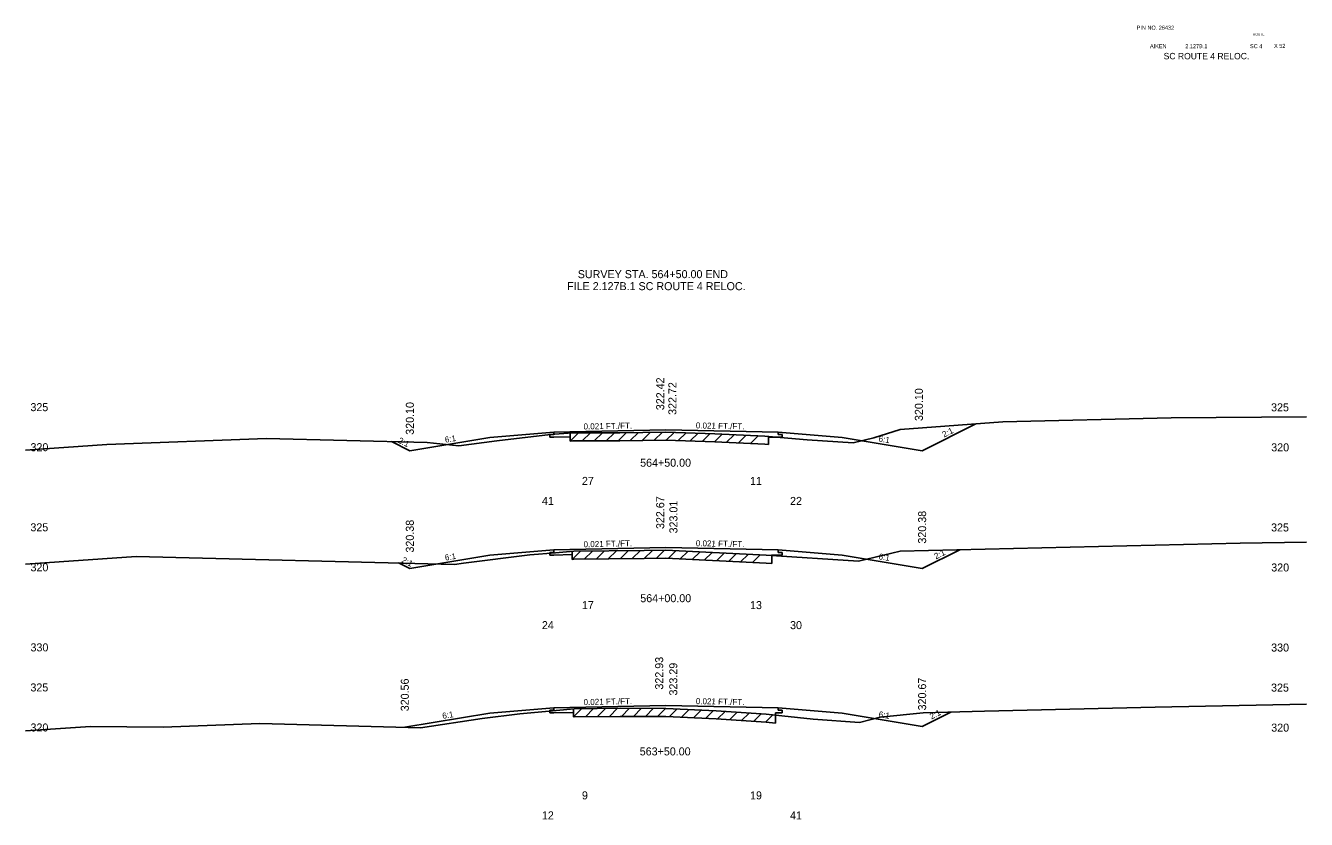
# Model space of a CAD drawing. Extents: x 2967 to 4323, y -3677 to -817.
# Drawn here: x 4005.3 to 4165.3, y -3560.8 to -3461.7 of the extents above; entities that cross this region are included whole.
import ezdxf

# ---------------------------------------------------------------- set-up
doc = ezdxf.new("R2010")
doc.units = 0
for name, color, linetype in [('Level 1', 7, 'Continuous'), ('Level 10', 7, 'Continuous'), ('Level 11', 7, 'Continuous'), ('Level 12', 7, 'Continuous'), ('Level 20', 7, 'Continuous'), ('Level 3', 7, 'Continuous'), ('Level 32', 7, 'Continuous'), ('Level 33', 7, 'Continuous'), ('Level 59', 7, 'Continuous'), ('Level 6', 7, 'Continuous'), ('Level 60', 7, 'Continuous'), ('Level 61', 7, 'Continuous'), ('Level 7', 7, 'Continuous')]:
    doc.layers.add(name, color=color, linetype=linetype)

msp = doc.modelspace()

# ---------------------------------------------------------------- linework, layer by layer
at = {"layer": 'Level 11'}
for p, q in [((4071.26, -3512.71), (4070.76, -3512.72)), ((4070.76, -3512.72), (4070.76, -3513.06)), ((4070.76, -3513.06), (4071.26, -3513.05)), ((4071.26, -3512.41), (4071.26, -3512.71)), ((4099.26, -3512.71), (4099.26, -3512.41)), ((4099.76, -3512.72), (4099.26, -3512.71)), ((4099.26, -3513.05), (4099.76, -3513.06)), ((4099.76, -3513.06), (4099.76, -3512.72)), ((4071.26, -3527.43), (4070.76, -3527.44)), ((4070.76, -3527.44), (4070.76, -3527.78)), ((4070.76, -3527.78), (4071.26, -3527.77)), ((4071.26, -3527.13), (4071.26, -3527.43)), ((4099.26, -3527.43), (4099.26, -3527.13)), ((4099.76, -3527.44), (4099.26, -3527.43)), ((4099.26, -3527.77), (4099.76, -3527.78)), ((4099.76, -3527.78), (4099.76, -3527.44)), ((4071.26, -3547.14), (4070.76, -3547.15)), ((4070.76, -3547.15), (4070.76, -3547.49)), ((4071.26, -3546.84), (4071.26, -3547.14)), ((4099.26, -3547.14), (4099.26, -3546.84)), ((4099.76, -3547.15), (4099.26, -3547.14)), ((4099.76, -3547.49), (4099.76, -3547.15)), ((4070.76, -3547.49), (4071.26, -3547.48)), ((4099.26, -3547.48), (4099.76, -3547.49))]:
    msp.add_line(p, q, dxfattribs=at)
at = {"layer": 'Level 12'}
for p, q in [((4073.3, -3513.01), (4071.26, -3513.05)), ((4073.3, -3512.53), (4073.3, -3513.01)), ((4098.05, -3512.96), (4098.05, -3513.03)), ((4098.05, -3513.03), (4099.26, -3513.05)), ((4073.55, -3527.72), (4071.26, -3527.77)), ((4073.55, -3527.32), (4073.55, -3527.72)), ((4098.5, -3527.84), (4098.5, -3527.75)), ((4098.5, -3527.75), (4099.26, -3527.77)), ((4073.71, -3546.98), (4073.71, -3547.43)), ((4073.71, -3547.43), (4071.26, -3547.48)), ((4098.96, -3547.78), (4098.96, -3547.47)), ((4098.96, -3547.47), (4099.26, -3547.48))]:
    msp.add_line(p, q, dxfattribs=at)
at = {"layer": 'Level 59'}
for p, q in [((4071.26, -3512.41), (4085.26, -3512.12)), ((4085.26, -3512.12), (4099.26, -3512.41)), ((4071.26, -3527.13), (4085.26, -3526.83)), ((4085.26, -3526.83), (4099.26, -3527.13)), ((4071.26, -3546.84), (4085.26, -3546.55)), ((4085.26, -3546.55), (4099.26, -3546.84))]:
    msp.add_line(p, q, dxfattribs=at)
at = {"layer": 'Level 6'}
for p, q in [((4063.26, -3513.08), (4071.26, -3512.41)), ((4099.26, -3512.41), (4107.26, -3513.08)), ((4063.26, -3527.79), (4071.26, -3527.13)), ((4099.26, -3527.13), (4107.26, -3527.79)), ((4063.26, -3547.51), (4071.26, -3546.84)), ((4099.26, -3546.84), (4107.26, -3547.51))]:
    msp.add_line(p, q, dxfattribs=at)
at = {"layer": 'Level 60'}
for p, q in [((4114.53, -3512.07), (4127.35, -3511.15)), ((4127.35, -3511.15), (4148.38, -3510.64)), ((4148.38, -3510.64), (4165.26, -3510.52)), ((4015.42, -3513.96), (4035.37, -3513.21)), ((4035.37, -3513.21), (4055.44, -3513.71)), ((4059.39, -3514.11), (4064.14, -3513.5)), ((4064.14, -3513.5), (4070.82, -3512.73)), ((4070.82, -3512.73), (4073.58, -3512.51)), ((4073.58, -3512.51), (4079.51, -3512.49)), ((4079.51, -3512.49), (4085.26, -3512.42)), ((4085.26, -3512.42), (4091.37, -3512.62)), ((4091.37, -3512.62), (4097.62, -3512.93)), ((4097.62, -3512.93), (4102.91, -3513.39)), ((4102.91, -3513.39), (4108.65, -3513.77)), ((4108.65, -3513.77), (4111.22, -3513.14)), ((4111.22, -3513.14), (4114.53, -3512.07)), ((4005.26, -3514.66), (4015.42, -3513.96)), ((4055.44, -3513.71), (4059.39, -3514.11)), ((4114.52, -3527.29), (4157, -3526.27)), ((4157, -3526.27), (4165.26, -3526.18)), ((4005.26, -3528.89), (4019.09, -3527.94)), ((4019.09, -3527.94), (4058.86, -3528.93)), ((4059.98, -3528.79), (4068.26, -3527.73)), ((4068.26, -3527.73), (4071.46, -3527.48)), ((4071.46, -3527.48), (4073.75, -3527.3)), ((4073.75, -3527.3), (4082.55, -3527.2)), ((4082.55, -3527.2), (4085.26, -3527.17)), ((4085.26, -3527.17), (4097.79, -3527.79)), ((4097.79, -3527.79), (4109.29, -3528.55)), ((4109.29, -3528.55), (4114.52, -3527.29)), ((4058.86, -3528.93), (4059.98, -3528.79)), ((4069.76, -3547.36), (4073.77, -3546.97)), ((4073.77, -3546.97), (4079.52, -3546.91)), ((4079.52, -3546.91), (4085.26, -3546.92)), ((4085.26, -3546.92), (4091.52, -3547.23)), ((4125.07, -3547.27), (4146.36, -3546.76)), ((4146.36, -3546.76), (4165.26, -3546.4)), ((4054.61, -3549.33), (4062.31, -3548.18)), ((4062.31, -3548.18), (4067.02, -3547.58)), ((4067.02, -3547.58), (4069.76, -3547.36)), ((4091.52, -3547.23), (4097.77, -3547.65)), ((4097.77, -3547.65), (4103.64, -3548.28)), ((4103.64, -3548.28), (4109.42, -3548.66)), ((4109.42, -3548.66), (4112.01, -3548.03)), ((4112.01, -3548.03), (4117.4, -3547.48)), ((4117.4, -3547.48), (4125.07, -3547.27)), ((4005.26, -3549.74), (4013.38, -3549.18)), ((4013.38, -3549.18), (4022.46, -3549.26)), ((4022.46, -3549.26), (4034.54, -3548.82)), ((4034.54, -3548.82), (4054.61, -3549.33))]:
    msp.add_line(p, q, dxfattribs=at)
at = {"layer": 'Level 61'}
for p, q in [((4074.33, -3512.51), (4073.3, -3513.53)), ((4073.3, -3512.53), (4073.3, -3513.53)), ((4073.3, -3513.53), (4073.58, -3513.51)), ((4073.58, -3513.51), (4079.51, -3513.49)), ((4075.81, -3512.5), (4074.8, -3513.51)), ((4077.31, -3512.5), (4076.3, -3513.5)), ((4078.81, -3512.49), (4077.8, -3513.49)), ((4080.31, -3512.48), (4079.3, -3513.49)), ((4079.51, -3513.49), (4085.26, -3513.42)), ((4081.81, -3512.46), (4080.8, -3513.47)), ((4083.31, -3512.44), (4082.3, -3513.46)), ((4084.81, -3512.43), (4083.8, -3513.44)), ((4085.26, -3513.42), (4091.37, -3513.62)), ((4086.27, -3512.45), (4085.3, -3513.42)), ((4087.77, -3512.5), (4086.8, -3513.47)), ((4089.27, -3512.55), (4088.3, -3513.52)), ((4090.77, -3512.6), (4089.8, -3513.57)), ((4092.26, -3512.66), (4091.3, -3513.62)), ((4093.76, -3512.74), (4092.8, -3513.69)), ((4095.26, -3512.81), (4094.3, -3513.76)), ((4096.76, -3512.88), (4095.8, -3513.84)), ((4098.05, -3513.96), (4098.05, -3512.96)), ((4091.37, -3513.62), (4097.62, -3513.93)), ((4097.62, -3513.93), (4098.05, -3513.96)), ((4074.58, -3527.29), (4073.55, -3528.32)), ((4073.55, -3527.32), (4073.55, -3528.32)), ((4076.07, -3527.28), (4075.05, -3528.29)), ((4077.57, -3527.26), (4076.55, -3528.27)), ((4079.07, -3527.24), (4078.05, -3528.25)), ((4080.57, -3527.22), (4079.55, -3528.24)), ((4082.07, -3527.21), (4081.05, -3528.22)), ((4083.57, -3527.19), (4082.55, -3528.2)), ((4085.07, -3527.17), (4084.05, -3528.19)), ((4086.51, -3527.23), (4085.55, -3528.19)), ((4088.01, -3527.31), (4087.05, -3528.26)), ((4089.51, -3527.38), (4088.55, -3528.33)), ((4091.01, -3527.46), (4090.05, -3528.41)), ((4092.51, -3527.53), (4091.55, -3528.48)), ((4094.01, -3527.6), (4093.05, -3528.56)), ((4095.51, -3527.68), (4094.55, -3528.63)), ((4097.01, -3527.75), (4096.05, -3528.71)), ((4098.5, -3528.84), (4098.5, -3527.84)), ((4073.55, -3528.32), (4073.75, -3528.3)), ((4073.75, -3528.3), (4082.55, -3528.2)), ((4082.55, -3528.2), (4085.26, -3528.17)), ((4085.26, -3528.17), (4097.79, -3528.79)), ((4097.79, -3528.79), (4098.5, -3528.84)), ((4074.72, -3546.96), (4073.71, -3547.98)), ((4073.71, -3546.98), (4073.71, -3547.98)), ((4076.22, -3546.94), (4075.21, -3547.96)), ((4077.72, -3546.93), (4076.71, -3547.94)), ((4079.22, -3546.91), (4078.21, -3547.92)), ((4080.71, -3546.91), (4079.71, -3547.91)), ((4082.21, -3546.91), (4081.21, -3547.91)), ((4083.71, -3546.91), (4082.71, -3547.91)), ((4085.21, -3546.92), (4084.21, -3547.91)), ((4086.66, -3546.99), (4085.71, -3547.94)), ((4088.16, -3547.06), (4087.21, -3548.01)), ((4089.66, -3547.13), (4088.71, -3548.09)), ((4073.71, -3547.98), (4073.77, -3547.97)), ((4073.77, -3547.97), (4079.52, -3547.91)), ((4079.52, -3547.91), (4085.26, -3547.92)), ((4085.26, -3547.92), (4091.52, -3548.23)), ((4091.16, -3547.21), (4090.21, -3548.16)), ((4091.52, -3548.23), (4097.77, -3548.65)), ((4092.64, -3547.3), (4091.71, -3548.24)), ((4094.14, -3547.41), (4093.21, -3548.34)), ((4095.64, -3547.51), (4094.71, -3548.44)), ((4097.14, -3547.61), (4096.21, -3548.55)), ((4098.61, -3547.74), (4097.71, -3548.65)), ((4097.77, -3548.65), (4098.96, -3548.78)), ((4098.96, -3548.78), (4098.96, -3547.78))]:
    msp.add_line(p, q, dxfattribs=at)
at = {"layer": 'Level 7'}
for p, q in [((4117.26, -3514.75), (4123.98, -3511.39)), ((4053.26, -3514.75), (4063.26, -3513.08)), ((4107.26, -3513.08), (4117.26, -3514.75)), ((4050.97, -3513.6), (4053.26, -3514.75)), ((4053.26, -3529.46), (4063.26, -3527.79)), ((4107.26, -3527.79), (4117.26, -3529.46)), ((4117.26, -3529.46), (4121.95, -3527.11)), ((4051.86, -3528.76), (4053.26, -3529.46)), ((4052.63, -3549.28), (4063.26, -3547.51)), ((4107.26, -3547.51), (4117.26, -3549.17)), ((4117.26, -3549.17), (4120.83, -3547.39))]:
    msp.add_line(p, q, dxfattribs=at)

# ---------------------------------------------------------------- texts
at = {"layer": 'Level 1'}
for s, p in [('SURVEY STA. 564+50.00 END', (4074.24, -3493.19)), ('FILE 2.127B.1 SC ROUTE 4 RELOC.', (4072.91, -3494.69)), ('27', (4074.76, -3519.01)), ('11', (4095.76, -3519.01)), ('41', (4069.76, -3521.51)), ('22', (4100.76, -3521.51)), ('17', (4074.76, -3534.52)), ('13', (4095.76, -3534.52)), ('24', (4069.76, -3537.02)), ('30', (4100.76, -3537.02)), ('9', (4074.76, -3558.28)), ('19', (4095.76, -3558.28)), ('12', (4069.76, -3560.78)), ('41', (4100.76, -3560.78))]:
    msp.add_text(s, height=1, dxfattribs=at).set_placement(p)
at = {"layer": 'Level 10'}
for s, p in [('322.42', (4085.04, -3509.68)), ('322.67', (4085.04, -3524.52)), ('322.93', (4084.91, -3544.57))]:
    msp.add_text(s, height=1, rotation=90, dxfattribs=at).set_placement(p)
for s, p in [('564+50.00', (4082.03, -3516.74)), ('564+00.00', (4082.05, -3533.66)), ('563+50.00', (4081.98, -3552.79))]:
    msp.add_text(s, height=1, dxfattribs=at).set_placement(p)
at = {"layer": 'Level 20'}
for s, height, p in [('PIN NO. 26432', 0.5, (4144.06, -3462.16)), ('AIKEN', 0.5, (4145.72, -3464.47)), (' 2.127B.1', 0.5, (4149.94, -3464.47)), ('SC 4', 0.5, (4158.22, -3464.47)), ('ROUTE', 0.3, (4158.59, -3462.9)), ('X 52', 0.5, (4161.22, -3464.43)), ('SC ROUTE 4 RELOC.', 0.8, (4147.43, -3465.86))]:
    msp.add_text(s, height=height, dxfattribs=at).set_placement(p)
at = {"layer": 'Level 3'}
for s, p in [(' 325', (4005.49, -3509.8)), (' 325', (4160.48, -3509.82)), (' 320', (4005.5, -3514.8)), (' 320', (4160.5, -3514.82)), (' 325', (4005.49, -3524.8)), (' 325', (4160.48, -3524.82)), (' 320', (4005.5, -3529.8)), (' 320', (4160.5, -3529.82)), (' 330', (4005.5, -3539.8)), (' 330', (4160.49, -3539.82)), (' 325', (4005.49, -3544.8)), (' 325', (4160.48, -3544.82)), (' 320', (4005.5, -3549.8)), (' 320', (4160.5, -3549.82))]:
    msp.add_text(s, height=1, dxfattribs=at).set_placement(p)
at = {"layer": 'Level 32'}
for s, rotation, p in [('0.021 FT./FT.', 1.1916, (4074.97, -3512.09)), ('0.021 FT./FT.', 358.8084, (4088.98, -3511.95)), ('2:1', 26.5651, (4120, -3513.1)), ('2:1', 333.435, (4051.72, -3513.7)), ('6:1', 9.4623, (4057.7, -3513.75)), ('6:1', 350.5377, (4111.78, -3513.58)), ('0.021 FT./FT.', 1.1916, (4074.97, -3526.8)), ('0.021 FT./FT.', 358.8084, (4088.98, -3526.66)), ('6:1', 9.4623, (4057.7, -3528.47)), ('6:1', 350.5377, (4111.78, -3528.29)), ('2:1', 26.5651, (4118.99, -3528.32)), ('2:1', 333.435, (4052.16, -3528.63)), ('0.021 FT./FT.', 1.1916, (4074.97, -3546.51)), ('0.021 FT./FT.', 358.8084, (4088.98, -3546.38)), ('2:1', 26.5651, (4118.43, -3548.31)), ('6:1', 9.4623, (4057.38, -3548.23)), ('6:1', 350.5377, (4111.78, -3548))]:
    msp.add_text(s, height=0.75, rotation=rotation, dxfattribs=at).set_placement(p)
at = {"layer": 'Level 33'}
for s, p in [('320.10', (4117.35, -3511.03)), ('320.10', (4053.76, -3512.75)), ('320.38', (4117.76, -3526.34)), ('320.38', (4053.76, -3527.46)), ('320.56', (4053.13, -3547.28)), ('320.67', (4117.76, -3547.17))]:
    msp.add_text(s, height=1, rotation=90, dxfattribs=at).set_placement(p)
at = {"layer": 'Level 59'}
for s, p in [(' 322.72', (4086.56, -3510.64)), (' 323.01', (4086.69, -3525.44)), (' 323.29', (4086.67, -3545.68))]:
    msp.add_text(s, height=1, rotation=90, dxfattribs=at).set_placement(p)

doc.saveas('drawing.dxf')
